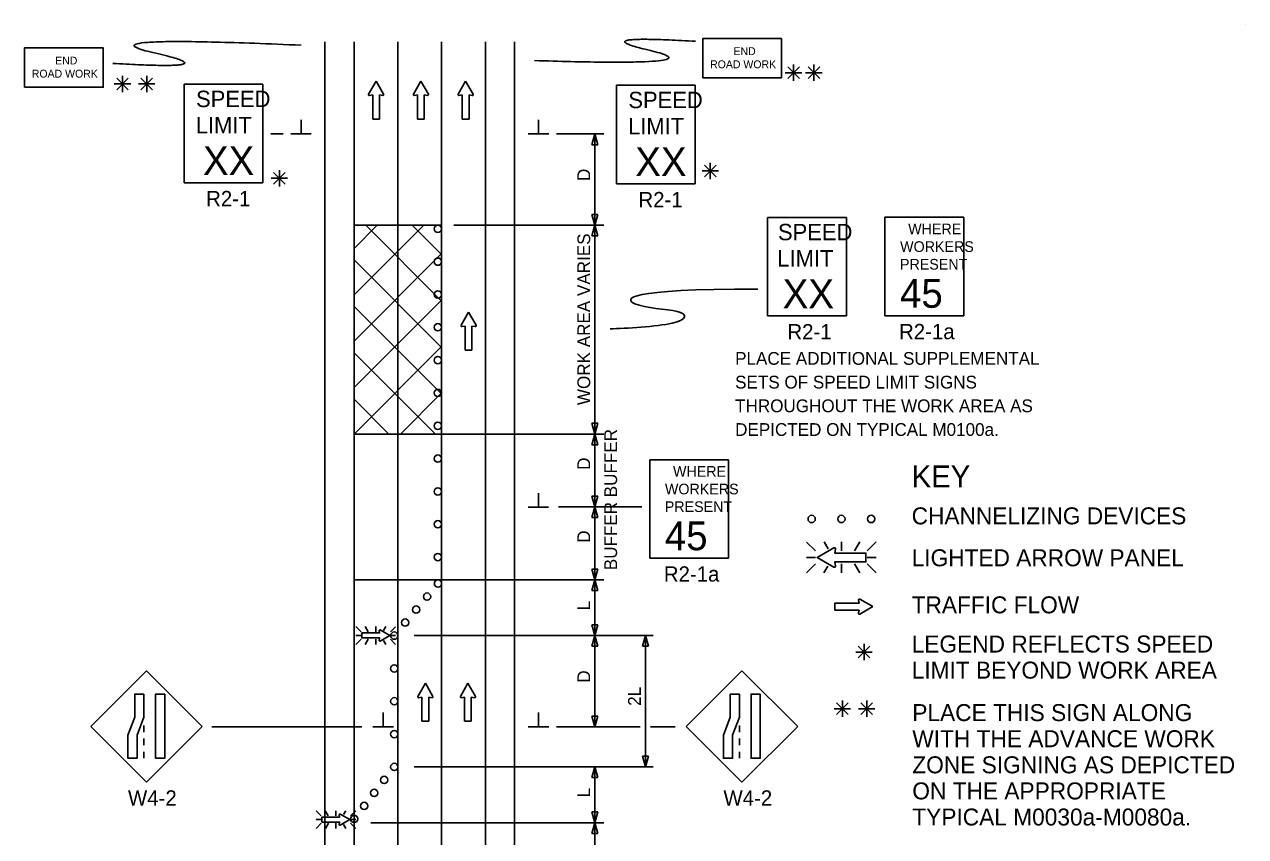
# Model space of a CAD drawing. Extents: x 16576 to 19504, y 5728 to 6974.
# Drawn here: x 17781 to 18451, y 6485 to 6931 of the extents above; entities that cross this region are included whole.
import ezdxf

# ---------------------------------------------------------------- set-up
doc = ezdxf.new("R2010")
doc.units = 0
for name, color, linetype in [('ALI_LEGAL_EX', 7, 'Continuous'), ('BORDER', 7, 'Continuous'), ('MT_SCRATCH_LEVEL_A', 7, 'Continuous'), ('MT_SCRATCH_LEVEL_E', 7, 'Continuous'), ('PAVT_EDGE_EX', 7, 'Continuous'), ('TRAFFIC_SIGNS_PR', 7, 'Continuous'), ('TYPICAL_TEXT_DIMEN_EX', 7, 'Continuous'), ('TYPICAL_TEXT_DIMEN_PR', 7, 'Continuous')]:
    doc.layers.add(name, color=color, linetype=linetype)

msp = doc.modelspace()

# ---------------------------------------------------------------- linework, layer by layer
at = {"layer": 'ALI_LEGAL_EX'}
for p, q in [((17985.63, 6921.33), (17985.63, 6077.19)), ((18009.63, 6921.33), (18009.63, 6077.19))]:
    msp.add_line(p, q, dxfattribs=at)
for points in [[(17985.63, 6921.33), (17985.63, 6896.33)], [(18009.63, 6921.33), (18009.63, 6896.33)], [(17985.63, 6821.33), (17985.63, 6796.33)], [(18009.63, 6821.33), (18009.63, 6796.33)], [(17985.63, 6721.33), (17985.63, 6696.33)], [(18009.63, 6721.33), (18009.63, 6696.33)], [(17985.63, 6621.33), (17985.63, 6596.33)], [(18009.63, 6521.33), (18009.63, 6496.33)]]:
    msp.add_lwpolyline(points, dxfattribs=at)
at = {"layer": 'BORDER'}
msp.add_line((18450.55, 6930.8), (18450.55, 6930.8), dxfattribs=at)
at = {"layer": 'MT_SCRATCH_LEVEL_A'}
msp.add_line((18009.63, 6820.72), (17961.63, 6820.72), dxfattribs=at)
at = {"layer": 'MT_SCRATCH_LEVEL_E'}
for p, q in [((17973.65, 6899.76), (17969.54, 6892.52)), ((17977.8, 6892.52), (17973.65, 6899.76)), ((17998.21, 6899.76), (17994.1, 6892.52)), ((18002.35, 6892.52), (17998.21, 6899.76)), ((18022.77, 6899.76), (18018.65, 6892.52)), ((18026.91, 6892.52), (18022.77, 6899.76)), ((17970.02, 6891.84), (17971.8, 6892.15)), ((17971.8, 6892.15), (17971.8, 6878.9)), ((17975.54, 6878.9), (17975.54, 6892.15)), ((17975.54, 6892.15), (17977.32, 6891.84)), ((17994.58, 6891.84), (17996.35, 6892.15)), ((17996.35, 6892.15), (17996.35, 6878.9)), ((18000.1, 6878.9), (18000.1, 6892.15)), ((18000.1, 6892.15), (18001.87, 6891.84)), ((18019.14, 6891.84), (18020.91, 6892.15)), ((18020.91, 6892.15), (18020.91, 6878.9)), ((18024.66, 6878.9), (18024.66, 6892.15)), ((18024.66, 6892.15), (18026.43, 6891.84)), ((17971.8, 6878.9), (17975.54, 6878.9)), ((17996.35, 6878.9), (18000.1, 6878.9)), ((18020.91, 6878.9), (18024.66, 6878.9)), ((18024.38, 6773.03), (18020.27, 6765.79)), ((18028.53, 6765.79), (18024.38, 6773.03)), ((18020.75, 6765.1), (18022.53, 6765.42)), ((18022.53, 6765.42), (18022.53, 6752.16)), ((18026.27, 6752.16), (18026.27, 6765.42)), ((18026.27, 6765.42), (18028.05, 6765.1)), ((18022.53, 6752.16), (18026.27, 6752.16)), ((18238.58, 6613.4), (18225.33, 6613.4)), ((18225.33, 6613.4), (18225.33, 6609.66)), ((18238.27, 6615.18), (18238.58, 6613.4)), ((18246.19, 6611.55), (18238.95, 6615.66)), ((18238.95, 6607.4), (18246.19, 6611.55)), ((18225.33, 6609.66), (18238.58, 6609.66)), ((18238.58, 6609.66), (18238.27, 6607.88)), ((18000.69, 6569.53), (17996.58, 6562.29)), ((18004.83, 6562.29), (18000.69, 6569.53)), ((18024.01, 6569.53), (18019.89, 6562.29)), ((18028.15, 6562.29), (18024.01, 6569.53)), ((17997.06, 6561.6), (17998.83, 6561.92)), ((17998.83, 6561.92), (17998.83, 6548.66)), ((18002.58, 6548.66), (18002.58, 6561.92)), ((18002.58, 6561.92), (18004.35, 6561.6)), ((18020.38, 6561.6), (18022.15, 6561.92)), ((18022.15, 6561.92), (18022.15, 6548.66)), ((18025.9, 6548.66), (18025.9, 6561.92)), ((18025.9, 6561.92), (18027.67, 6561.6)), ((17998.83, 6548.66), (18002.58, 6548.66)), ((18022.15, 6548.66), (18025.9, 6548.66))]:
    msp.add_line(p, q, dxfattribs=at)
for centre, start, end in [((17969.94, 6892.3), 150.42484, 279.96381), ((17977.39, 6892.3), 260.03619, 29.77312), ((17994.5, 6892.3), 150.42484, 279.96381), ((18001.94, 6892.3), 260.03619, 29.77312), ((18019.06, 6892.3), 150.42484, 279.96381), ((18026.5, 6892.3), 260.03619, 29.77312), ((18020.68, 6765.56), 150.42484, 279.96381), ((18028.12, 6765.57), 260.03619, 29.77312), ((18238.73, 6615.25), 60.42484, 189.96381), ((18238.73, 6607.81), 170.03619, 299.77312), ((17996.98, 6562.06), 150.42484, 279.96381), ((18004.42, 6562.06), 260.03619, 29.77312), ((18020.3, 6562.06), 150.42484, 279.96381), ((18027.74, 6562.06), 260.03619, 29.77312)]:
    msp.add_arc(centre, 0.463, start, end, dxfattribs=at)
at = {"layer": 'PAVT_EDGE_EX'}
for p, q in [((17945.63, 6921.33), (17945.63, 5988.51)), ((17961.63, 6921.33), (17961.63, 5988.51)), ((18033.63, 6921.33), (18033.63, 5988.51)), ((18049.63, 6921.33), (18049.63, 5988.51)), ((18009.63, 6820.72), (17961.63, 6820.72)), ((17961.63, 6820.72), (17961.63, 6706.19)), ((17961.63, 6808.01), (17974.35, 6820.72)), ((17961.63, 6782.55), (17999.8, 6820.72)), ((18009.63, 6779.1), (17968.01, 6820.72)), ((18009.63, 6804.56), (17993.47, 6820.72)), ((17961.63, 6757.1), (18009.63, 6805.1)), ((18009.63, 6753.65), (17961.63, 6801.65)), ((17961.63, 6731.64), (18009.63, 6779.64)), ((18009.63, 6728.19), (17961.63, 6776.19)), ((17961.63, 6706.19), (18009.63, 6754.19)), ((18006.18, 6706.19), (17961.63, 6750.73)), ((17980.73, 6706.19), (17961.63, 6725.28)), ((17987.09, 6706.19), (18009.63, 6728.73))]:
    msp.add_line(p, q, dxfattribs=at)
msp.add_lwpolyline([(18009.63, 6706.19), (17961.63, 6706.19), (17961.63, 6626.19), (18009.63, 6626.19)], close=True, dxfattribs=at)
at = {"layer": 'TRAFFIC_SIGNS_PR'}
for p, q in [((17868.44, 6897.99), (17911.64, 6897.99)), ((17868.44, 6843.99), (17868.44, 6897.99)), ((17911.64, 6843.99), (17911.64, 6897.99)), ((18105.54, 6897.41), (18148.74, 6897.41)), ((18105.54, 6843.41), (18105.54, 6897.41)), ((18148.74, 6843.41), (18148.74, 6897.41)), ((17868.44, 6843.99), (17911.64, 6843.99)), ((18105.54, 6843.41), (18148.74, 6843.41)), ((18188.43, 6824.97), (18231.63, 6824.97)), ((18188.43, 6770.97), (18188.43, 6824.97)), ((18231.63, 6770.97), (18231.63, 6824.97)), ((18252.77, 6825.07), (18295.97, 6825.07)), ((18252.77, 6771.07), (18252.77, 6825.07)), ((18295.97, 6771.07), (18295.97, 6825.07)), ((18188.43, 6770.97), (18231.63, 6770.97)), ((18252.77, 6771.07), (18295.97, 6771.07)), ((18123.78, 6692.12), (18166.98, 6692.12)), ((18123.78, 6638.12), (18123.78, 6692.12)), ((18166.98, 6638.12), (18166.98, 6692.12)), ((18209.78, 6646.97), (18214.71, 6642.04)), ((18221.54, 6643.15), (18219.33, 6646.98)), ((18228.86, 6642.04), (18228.86, 6646.98)), ((18236.1, 6642.04), (18238.95, 6646.98)), ((18243.01, 6642.04), (18247.95, 6646.98)), ((18123.78, 6638.12), (18166.98, 6638.12)), ((18214.71, 6638.49), (18209.78, 6638.49)), ((18243.01, 6638.49), (18247.95, 6638.49)), ((18209.78, 6630), (18214.71, 6634.93)), ((18219.29, 6630), (18221.4, 6633.66)), ((18228.86, 6634.93), (18228.86, 6630)), ((18238.99, 6630), (18236.14, 6634.93)), ((18243.01, 6634.93), (18247.95, 6629.99)), ((17965.41, 6597.73), (17962.59, 6600.55)), ((17967.71, 6600.55), (17969.33, 6597.73)), ((17973.49, 6597.73), (17973.49, 6600.55)), ((17978.96, 6600.55), (17977.76, 6598.45)), ((17984.4, 6600.54), (17981.58, 6597.73)), ((17965.41, 6595.69), (17962.59, 6595.69)), ((17965.41, 6593.66), (17962.59, 6590.84)), ((17969.36, 6593.66), (17967.73, 6590.84)), ((17973.49, 6593.66), (17973.49, 6590.84)), ((17977.68, 6593.03), (17978.94, 6590.84)), ((17981.58, 6595.69), (17984.4, 6595.69)), ((17984.4, 6590.84), (17981.58, 6593.66)), ((17847.75, 6576.37), (17817.2, 6545.83)), ((17878.3, 6545.83), (17847.75, 6576.37)), ((18174.35, 6576.37), (18143.81, 6545.83)), ((18204.9, 6545.83), (18174.35, 6576.37)), ((17817.2, 6545.83), (17847.75, 6515.28)), ((17846.35, 6546.38), (17846.35, 6542.78)), ((17847.75, 6515.28), (17878.3, 6545.83)), ((18143.81, 6545.83), (18174.35, 6515.28)), ((18172.95, 6546.38), (18172.95, 6542.78)), ((18174.35, 6515.28), (18204.9, 6545.83)), ((17846.35, 6539.18), (17846.35, 6535.58)), ((18172.95, 6539.18), (18172.95, 6535.58)), ((17846.35, 6531.98), (17846.35, 6528.38)), ((18172.95, 6531.98), (18172.95, 6528.38)), ((17943.54, 6496.77), (17940.72, 6499.59)), ((17945.83, 6499.59), (17947.46, 6496.77)), ((17951.62, 6496.77), (17951.62, 6499.59)), ((17957.09, 6499.59), (17955.88, 6497.5)), ((17962.53, 6499.59), (17959.71, 6496.77)), ((17943.54, 6494.74), (17940.72, 6494.74)), ((17943.54, 6492.71), (17940.72, 6489.89)), ((17947.49, 6492.71), (17945.86, 6489.89)), ((17951.62, 6492.71), (17951.62, 6489.89)), ((17955.8, 6492.07), (17957.06, 6489.89)), ((17959.71, 6494.74), (17962.53, 6494.74)), ((17962.53, 6489.89), (17959.71, 6492.71))]:
    msp.add_line(p, q, dxfattribs=at)
for points in [[(18152.81, 6901.44), (18196.01, 6901.44), (18196.01, 6923.04), (18152.81, 6923.04)], [(17780.8, 6896.31), (17823.99, 6896.31), (17823.99, 6917.91), (17780.8, 6917.91)], [(17846.35, 6563.53), (17846.35, 6550.95), (17842.58, 6540.96), (17842.58, 6528.38), (17837.53, 6528.38), (17837.53, 6540.96), (17841.29, 6550.95), (17841.29, 6563.53)], [(17857.75, 6563.53), (17857.75, 6528.38), (17852.7, 6528.38), (17852.7, 6563.53)], [(18172.95, 6563.53), (18172.95, 6550.95), (18169.19, 6540.96), (18169.19, 6528.38), (18164.13, 6528.38), (18164.13, 6540.96), (18167.89, 6550.95), (18167.89, 6563.53)], [(18184.35, 6563.53), (18184.35, 6528.38), (18179.3, 6528.38), (18179.3, 6563.53)]]:
    msp.add_lwpolyline(points, close=True, dxfattribs=at)
for points in [[(18224.79, 6643.76), (18215.5, 6638.49), (18224.79, 6633.17)], [(18225.66, 6633.79), (18225.26, 6636.06), (18242.28, 6636.06), (18242.28, 6640.86), (18225.26, 6640.86), (18225.67, 6643.14)], [(17975.32, 6598.38), (17975.55, 6597.08), (17965.83, 6597.08), (17965.83, 6594.34), (17975.55, 6594.34), (17975.32, 6593.03)], [(17975.82, 6592.68), (17981.13, 6595.69), (17975.82, 6598.73)], [(17953.45, 6497.42), (17953.68, 6496.13), (17943.96, 6496.13), (17943.96, 6493.38), (17953.68, 6493.38), (17953.45, 6492.08)], [(17953.95, 6491.73), (17959.26, 6494.74), (17953.95, 6497.78)]]:
    msp.add_lwpolyline(points, dxfattribs=at)
for centre in [(18007.53, 6818.71), (18007.53, 6800.71), (18007.53, 6782.71), (18007.53, 6764.71), (18007.53, 6746.71), (18007.53, 6728.71), (18007.53, 6710.71), (18007.53, 6692.71), (18007.53, 6674.71), (18007.53, 6656.71), (18212.57, 6659.6), (18228.87, 6659.6), (18245.17, 6659.6), (18007.53, 6638.71), (18007.63, 6624.19), (18001.63, 6617.04), (17995.63, 6609.9), (17989.63, 6602.76), (17983.63, 6595.62), (17983.63, 6577.62), (17983.63, 6559.62), (17983.63, 6541.62), (17983.63, 6523.62), (17978.14, 6516.49), (17972.64, 6509.36), (17967.14, 6502.23), (17961.64, 6495.11)]:
    msp.add_circle(centre, 2, dxfattribs=at)
for centre, radius, start, end in [((18225.08, 6643.24), 0.598, 350.73078, 118.89165), ((18225.08, 6633.69), 0.597, 241.48329, 9.95933), ((17975.66, 6598.43), 0.341, 61.48329, 189.95933), ((17975.66, 6592.98), 0.341, 170.73078, 298.89165), ((17953.78, 6497.48), 0.341, 61.48329, 189.95933), ((17953.78, 6492.03), 0.341, 170.73078, 298.89165)]:
    msp.add_arc(centre, radius, start, end, dxfattribs=at)
for points in [[(17829.27, 6909.42), (17894.43, 6905.55), (17809.41, 6924.9), (17932.51, 6919.41)], [(18148.92, 6921.54), (18086.6, 6925.24), (18161.65, 6907.71), (18060.63, 6910.98)]]:
    msp.add_open_spline(points, degree=2, dxfattribs=at)
at = {"layer": 'TYPICAL_TEXT_DIMEN_EX'}
for p, q in [((18241.27, 6586.62), (18241.27, 6591.07)), ((18241.27, 6586.62), (18236.73, 6586.62)), ((18238.08, 6589.81), (18244.45, 6583.43)), ((18244.45, 6589.81), (18238.08, 6583.43)), ((18241.27, 6586.62), (18244.45, 6586.62)), ((18241.27, 6586.62), (18245.74, 6586.62)), ((18241.27, 6586.62), (18241.27, 6582.12)), ((18226.25, 6558.74), (18232.63, 6552.36)), ((18232.63, 6558.74), (18226.25, 6552.36)), ((18229.44, 6555.55), (18229.44, 6560.01)), ((18239.57, 6558.74), (18245.95, 6552.36)), ((18245.95, 6558.74), (18239.57, 6552.36)), ((18242.76, 6555.55), (18242.76, 6560.01)), ((18229.44, 6555.55), (18224.91, 6555.55)), ((18229.44, 6555.55), (18232.63, 6555.55)), ((18229.44, 6555.55), (18233.92, 6555.55)), ((18229.44, 6555.55), (18229.44, 6551.05)), ((18242.76, 6555.55), (18238.23, 6555.55)), ((18242.76, 6555.55), (18245.95, 6555.55)), ((18242.76, 6555.55), (18247.24, 6555.55)), ((18242.76, 6555.55), (18242.76, 6551.05))]:
    msp.add_line(p, q, dxfattribs=at)
at = {"layer": 'TYPICAL_TEXT_DIMEN_PR'}
for p, q in [((18199.47, 6907.53), (18205.84, 6901.15)), ((18205.84, 6907.53), (18199.47, 6901.15)), ((18202.65, 6904.34), (18202.65, 6908.8)), ((18216.97, 6907.53), (18210.59, 6901.15)), ((18210.6, 6907.53), (18216.97, 6901.15)), ((18213.78, 6904.34), (18213.78, 6908.8)), ((17831.4, 6901.38), (17837.78, 6895.01)), ((17837.78, 6901.38), (17831.4, 6895.01)), ((17834.59, 6898.19), (17834.59, 6902.65)), ((17844.72, 6901.38), (17851.1, 6895.01)), ((17851.1, 6901.38), (17844.72, 6895.01)), ((17847.91, 6898.19), (17847.91, 6902.65)), ((18202.65, 6904.34), (18198.12, 6904.34)), ((18202.65, 6904.34), (18205.84, 6904.34)), ((18202.65, 6904.34), (18207.13, 6904.34)), ((18202.65, 6904.34), (18202.65, 6899.84)), ((18213.78, 6904.34), (18209.25, 6904.34)), ((18213.78, 6904.34), (18216.97, 6904.34)), ((18213.78, 6904.34), (18218.26, 6904.34)), ((18213.78, 6904.34), (18213.78, 6899.84)), ((17834.59, 6898.19), (17830.06, 6898.19)), ((17834.59, 6898.19), (17837.78, 6898.19)), ((17834.59, 6898.19), (17839.07, 6898.19)), ((17834.59, 6898.19), (17834.59, 6893.69)), ((17847.91, 6898.19), (17843.38, 6898.19)), ((17847.91, 6898.19), (17851.1, 6898.19)), ((17847.91, 6898.19), (17852.39, 6898.19)), ((17847.91, 6898.19), (17847.91, 6893.69)), ((17932.51, 6870.72), (17932.51, 6878.51)), ((18062.76, 6870.72), (18062.76, 6878.51)), ((17915.86, 6870.72), (17922.63, 6870.72)), ((17926.88, 6870.72), (17938.13, 6870.72)), ((18068.38, 6870.72), (18057.13, 6870.72)), ((18098.63, 6870.72), (18072.63, 6870.72)), ((18092.06, 6864.86), (18093.63, 6870.72)), ((18093.63, 6870.72), (18093.63, 6820.72)), ((18093.63, 6870.72), (18095.2, 6864.86)), ((18093.63, 6864.86), (18092.06, 6864.86)), ((18095.2, 6864.86), (18093.63, 6864.86)), ((18153.78, 6853.65), (18160.15, 6847.28)), ((18160.15, 6853.65), (18153.78, 6847.28)), ((18156.97, 6850.47), (18156.97, 6854.92)), ((17920.67, 6846.42), (17916.13, 6846.42)), ((17917.48, 6849.61), (17923.85, 6843.24)), ((17923.85, 6849.61), (17917.48, 6843.24)), ((17920.67, 6846.42), (17920.67, 6850.88)), ((17920.67, 6846.42), (17923.85, 6846.42)), ((17920.67, 6846.42), (17925.14, 6846.42)), ((17920.67, 6846.42), (17920.67, 6841.92)), ((18156.97, 6850.47), (18152.43, 6850.47)), ((18156.97, 6850.47), (18160.15, 6850.47)), ((18156.97, 6850.47), (18161.44, 6850.47)), ((18156.97, 6850.47), (18156.97, 6845.97)), ((18093.63, 6820.72), (18092.06, 6826.58)), ((18092.06, 6826.58), (18093.63, 6826.58)), ((18093.63, 6826.58), (18095.2, 6826.58)), ((18095.2, 6826.58), (18093.63, 6820.72)), ((18098.63, 6820.72), (18016.24, 6820.72)), ((18092.06, 6814.86), (18093.63, 6820.72)), ((18093.63, 6706.19), (18093.63, 6820.72)), ((18093.63, 6820.72), (18095.2, 6814.86)), ((18093.63, 6814.86), (18092.06, 6814.86)), ((18095.2, 6814.86), (18093.63, 6814.86)), ((18093.63, 6706.19), (18092.06, 6712.05)), ((18092.06, 6712.05), (18093.63, 6712.05)), ((18093.63, 6712.05), (18095.2, 6712.05)), ((18095.2, 6712.05), (18093.63, 6706.19)), ((18098.63, 6706.19), (18009.63, 6706.19)), ((18092.06, 6700.32), (18093.63, 6706.19)), ((18093.63, 6676.76), (18093.63, 6706.19)), ((18093.63, 6706.19), (18095.2, 6700.32)), ((18093.63, 6666.19), (18093.63, 6706.19)), ((18093.63, 6700.32), (18092.06, 6700.32)), ((18095.2, 6700.32), (18093.63, 6700.32)), ((18062.67, 6666.03), (18062.67, 6673.82)), ((18093.63, 6666.19), (18092.06, 6672.05)), ((18092.06, 6672.05), (18093.63, 6672.05)), ((18093.63, 6672.05), (18095.2, 6672.05)), ((18095.2, 6672.05), (18093.63, 6666.19)), ((18068.3, 6666.03), (18057.05, 6666.03)), ((18119.41, 6666.19), (18073.7, 6666.19)), ((18092.06, 6660.32), (18093.63, 6666.19)), ((18093.63, 6626.19), (18093.63, 6666.19)), ((18093.63, 6666.19), (18095.2, 6660.32)), ((18093.63, 6660.32), (18092.06, 6660.32)), ((18095.2, 6660.32), (18093.63, 6660.32)), ((18093.63, 6626.19), (18092.06, 6632.05)), ((18092.06, 6632.05), (18093.63, 6632.05)), ((18093.63, 6632.05), (18095.2, 6632.05)), ((18095.2, 6632.05), (18093.63, 6626.19)), ((18098.63, 6626.19), (17961.63, 6626.19)), ((18092.06, 6620.32), (18093.63, 6626.19)), ((18093.63, 6595.62), (18093.63, 6626.19)), ((18093.63, 6626.19), (18095.2, 6620.32)), ((18093.63, 6620.32), (18092.06, 6620.32)), ((18095.2, 6620.32), (18093.63, 6620.32)), ((18093.63, 6595.62), (18092.06, 6601.48)), ((18092.06, 6601.48), (18093.63, 6601.48)), ((18093.63, 6601.48), (18095.2, 6601.48)), ((18095.2, 6601.48), (18093.63, 6595.62)), ((18125.68, 6595.62), (17994.53, 6595.62)), ((18092.06, 6589.76), (18093.63, 6595.62)), ((18093.63, 6595.62), (18093.63, 6545.62)), ((18093.63, 6595.62), (18095.2, 6589.76)), ((18119.87, 6589.76), (18121.44, 6595.62)), ((18121.44, 6595.62), (18123.01, 6589.76)), ((18121.44, 6595.62), (18121.44, 6523.62)), ((18093.63, 6589.76), (18092.06, 6589.76)), ((18095.2, 6589.76), (18093.63, 6589.76)), ((18121.44, 6589.76), (18119.87, 6589.76)), ((18123.01, 6589.76), (18121.44, 6589.76)), ((17977.56, 6545.62), (17977.56, 6553.41)), ((18062.76, 6545.62), (18062.76, 6553.41)), ((18093.63, 6545.62), (18092.06, 6551.48)), ((18092.06, 6551.48), (18093.63, 6551.48)), ((18093.63, 6551.48), (18095.2, 6551.48)), ((18095.2, 6551.48), (18093.63, 6545.62)), ((18121.44, 6550.49), (18121.44, 6546.72)), ((17883.63, 6545.62), (17965.83, 6545.62)), ((17983.19, 6545.62), (17971.94, 6545.62)), ((18068.38, 6545.62), (18057.13, 6545.62)), ((18118.54, 6545.62), (18072.63, 6545.62)), ((18137.63, 6545.62), (18124.11, 6545.62)), ((17994.53, 6523.62), (18125.68, 6523.62)), ((18092.06, 6517.76), (18093.63, 6523.62)), ((18093.63, 6493.06), (18093.63, 6523.62)), ((18093.63, 6523.62), (18095.2, 6517.76)), ((18121.44, 6523.62), (18119.87, 6529.48)), ((18119.87, 6529.48), (18121.44, 6529.48)), ((18121.44, 6529.48), (18123.01, 6529.48)), ((18123.01, 6529.48), (18121.44, 6523.62)), ((18093.63, 6517.76), (18092.06, 6517.76)), ((18095.2, 6517.76), (18093.63, 6517.76)), ((18093.63, 6493.06), (18092.06, 6498.92)), ((18092.06, 6498.92), (18093.63, 6498.92)), ((18093.63, 6498.92), (18095.2, 6498.92)), ((18095.2, 6498.92), (18093.63, 6493.06)), ((17970.8, 6493.06), (18098.63, 6493.06)), ((18092.06, 6487.2), (18093.63, 6493.06)), ((18093.63, 6493.06), (18093.63, 6453.06)), ((18093.63, 6493.06), (18095.2, 6487.2)), ((18093.63, 6487.2), (18092.06, 6487.2)), ((18095.2, 6487.2), (18093.63, 6487.2))]:
    msp.add_line(p, q, dxfattribs=at)
msp.add_open_spline([(18183.08, 6785.71), (18109.7, 6785.71), (18109.7, 6774.96), (18144.62, 6774.96), (18144.62, 6765.91), (18110.41, 6764.15), (18102.12, 6763.86)], degree=3, dxfattribs=at)

# ---------------------------------------------------------------- texts
at = {"layer": 'TRAFFIC_SIGNS_PR'}
for s, height, p in [('END', 4.31, (17797.67, 6908.83)), ('END', 4.31, (18169.69, 6913.96)), ('ROAD WORK', 4.31, (17784.85, 6901.64)), ('ROAD WORK', 4.31, (18156.87, 6906.77)), ('SPEED', 9, (17874.93, 6885.46)), ('SPEED', 9, (18112.03, 6884.88)), ('LIMIT', 9, (17874.75, 6871.06)), ('LIMIT', 9, (18111.85, 6870.48)), ('XX', 15.785, (17878.7, 6848.22)), ('XX', 15.785, (18115.8, 6847.64)), ('R2-1', 8.37, (17880.45, 6831.12)), ('R2-1', 8.37, (18117.55, 6830.54)), ('SPEED', 9, (18194.09, 6812.44)), ('WHERE', 5.85, (18265.5, 6815.71)), ('WORKERS', 5.85, (18261.08, 6806.04)), ('LIMIT', 9, (18193.71, 6798.04)), ('PRESENT', 5.85, (18261, 6796.36)), ('XX', 15.785, (18196.65, 6775.2)), ('45', 15.785, (18260.99, 6775.41)), ('R2-1', 8.37, (18199.24, 6758.1)), ('R2-1a', 8.37, (18260.48, 6758.2)), ('PLACE ADDITIONAL SUPPLEMENTAL', 7, (18170.58, 6744.15)), ('SETS OF SPEED LIMIT SIGNS', 7, (18170.58, 6731.15)), ('THROUGHOUT THE WORK AREA AS', 7, (18170.58, 6718.15)), ('DEPICTED ON TYPICAL M0100a.', 7, (18170.58, 6705.15)), ('WHERE', 5.85, (18136.51, 6682.77)), ('WORKERS', 5.85, (18132.09, 6673.09)), ('PRESENT', 5.85, (18132.01, 6663.42)), ('45', 15.785, (18132, 6642.46)), ('R2-1a', 8.37, (18131.49, 6625.25)), ('W4-2', 8.37, (17837.58, 6502.41)), ('W4-2', 8.37, (18164.18, 6502.41))]:
    msp.add_text(s, height=height, dxfattribs=at).set_placement(p)
at = {"layer": 'TYPICAL_TEXT_DIMEN_EX'}
for s, height, p in [('KEY', 12, (18267.41, 6676.96)), ('CHANNELIZING DEVICES', 9.3, (18267.41, 6656.66)), ('LIGHTED ARROW PANEL', 9.3, (18267.41, 6633.66)), ('TRAFFIC FLOW', 9.3, (18267.41, 6607.86)), ('LEGEND REFLECTS SPEED', 9.31, (18267.41, 6586.37)), ('LIMIT BEYOND WORK AREA', 9.31, (18267.41, 6572.06)), ('PLACE THIS SIGN ALONG', 9.31, (18267.76, 6548.75)), ('WITH THE ADVANCE WORK', 9.31, (18267.76, 6534.44)), ('ZONE SIGNING AS DEPICTED', 9.31, (18267.76, 6520.13)), ('ON THE APPROPRIATE', 9.31, (18267.76, 6505.82)), ('TYPICAL M0030a-M0080a.', 9.31, (18267.76, 6491.51))]:
    msp.add_text(s, height=height, dxfattribs=at).set_placement(p)
at = {"layer": 'TYPICAL_TEXT_DIMEN_PR'}
for s, p in [('D', (18091.08, 6844.94)), ('WORK AREA VARIES', (18091.08, 6722.04)), ('BUFFER', (18105.86, 6671.51)), ('D', (18091.08, 6686.53)), ('BUFFER', (18105.86, 6631.51)), ('D', (18091.08, 6646.53)), ('L', (18091.08, 6609.48)), ('D', (18091.08, 6569.84)), ('2L', (18118.88, 6557.13)), ('L', (18091.08, 6506.92))]:
    msp.add_text(s, height=7, rotation=90, dxfattribs=at).set_placement(p)

doc.saveas('drawing.dxf')
